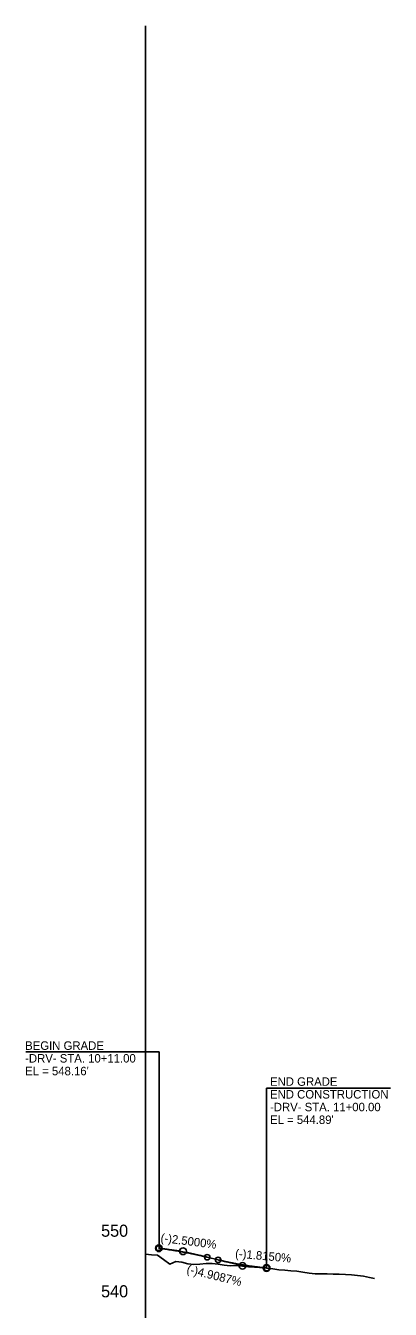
# Model space of a CAD drawing. Extents: x 1736530 to 1739201, y 695175 to 699135.
# Drawn here: x 1738900 to 1739201, y 696615 to 697675 of the extents above; entities that cross this region are included whole.
import ezdxf

# ---------------------------------------------------------------- set-up
doc = ezdxf.new("R2010")
doc.units = 0
for name, color, linetype in [('Exist Profile Cell', 7, 'Continuous'), ('Exist Vertical Profile Ground Line', 7, 'Continuous'), ('Exist Vertical Profile Vertical Axis Label', 7, 'Continuous'), ('Prop PFL Text', 7, 'Continuous'), ('Prop Vertical Profile Curve Label', 7, 'Continuous'), ('Prop Vertical Profile Grade', 7, 'Continuous'), ('Prop Vertical Profile Grade Label', 7, 'Continuous'), ('Prop VPI Label', 7, 'Continuous')]:
    doc.layers.add(name, color=color, linetype=linetype)

msp = doc.modelspace()

# ---------------------------------------------------------------- linework, layer by layer
at = {"layer": 'Exist Profile Cell'}
msp.add_line((1738999.2, 696424.5), (1738999.2, 697674.5), dxfattribs=at)
at = {"layer": 'Exist Vertical Profile Ground Line'}
msp.add_lwpolyline([(1738999.2, 696660.3), (1739004.2, 696659.9), (1739009.2, 696659.5), (1739014.2, 696656.1), (1739019.2, 696652.1), (1739024.2, 696654.3), (1739029.2, 696653.8), (1739034.2, 696652.4), (1739039.2, 696651.8), (1739044.2, 696652.3), (1739049.2, 696652.8), (1739054.2, 696652.8), (1739059.2, 696652.1), (1739064.2, 696651.3), (1739069.2, 696650.9), (1739074.2, 696651), (1739079.2, 696650.6), (1739084.2, 696650.1), (1739089.2, 696649.8), (1739094.2, 696649.5), (1739099.2, 696649), (1739104.2, 696648.4), (1739109.2, 696647.5), (1739114.2, 696647.1), (1739119.2, 696646.8), (1739124.2, 696646.4), (1739129.2, 696645.6), (1739134.2, 696644.8), (1739139.2, 696644.1), (1739144.2, 696644.1), (1739149.2, 696644.2), (1739154.2, 696644), (1739159.2, 696643.8), (1739164.2, 696643.6), (1739169.2, 696643.3), (1739174.2, 696642.7), (1739179.2, 696642.2), (1739184.2, 696641.1), (1739188.2, 696640.3)], dxfattribs=at)
at = {"layer": 'Prop Vertical Profile Curve Label'}
for centre in [(1739010.2, 696665.3), (1739050.2, 696657.9), (1739059.2, 696655.7), (1739099.2, 696649)]:
    msp.add_circle(centre, 2.25, dxfattribs=at)
at = {"layer": 'Prop Vertical Profile Grade'}
msp.add_line((1739050.2, 696657.9), (1739059.2, 696655.7), dxfattribs=at)
for points in [[(1739010.2, 696665.3), (1739011, 696665.2), (1739011.8, 696665.1), (1739012.6, 696665), (1739013.4, 696664.9), (1739014.2, 696664.8), (1739015, 696664.7), (1739015.8, 696664.6), (1739016.6, 696664.5), (1739017.4, 696664.4), (1739018.2, 696664.2), (1739019, 696664.1), (1739019.8, 696664), (1739020.6, 696663.9), (1739021.4, 696663.8), (1739022.2, 696663.6), (1739023, 696663.5), (1739023.8, 696663.4), (1739024.6, 696663.2), (1739025.4, 696663.1), (1739026.2, 696663), (1739027, 696662.8), (1739027.8, 696662.7), (1739028.6, 696662.5), (1739029.4, 696662.4), (1739030.2, 696662.2), (1739031, 696662.1), (1739031.8, 696661.9), (1739032.6, 696661.8), (1739033.4, 696661.6), (1739034.2, 696661.5), (1739035, 696661.3), (1739035.8, 696661.2), (1739036.6, 696661), (1739037.4, 696660.8), (1739038.2, 696660.7), (1739039, 696660.5), (1739039.8, 696660.3), (1739040.6, 696660.2), (1739041.4, 696660), (1739042.2, 696659.8), (1739043, 696659.6), (1739043.8, 696659.4), (1739044.6, 696659.3), (1739045.4, 696659.1), (1739046.2, 696658.9), (1739047, 696658.7), (1739047.8, 696658.5), (1739048.6, 696658.3), (1739049.4, 696658.1), (1739050.2, 696657.9)], [(1739059.2, 696655.7), (1739060, 696655.5), (1739060.8, 696655.3), (1739061.6, 696655.2), (1739062.4, 696655), (1739063.2, 696654.8), (1739064, 696654.6), (1739064.8, 696654.4), (1739065.6, 696654.2), (1739066.4, 696654.1), (1739067.2, 696653.9), (1739068, 696653.7), (1739068.8, 696653.6), (1739069.6, 696653.4), (1739070.4, 696653.2), (1739071.2, 696653.1), (1739072, 696652.9), (1739072.8, 696652.7), (1739073.6, 696652.6), (1739074.4, 696652.4), (1739075.2, 696652.3), (1739076, 696652.2), (1739076.8, 696652), (1739077.6, 696651.9), (1739078.4, 696651.7), (1739079.2, 696651.6), (1739080, 696651.5), (1739080.8, 696651.3), (1739081.6, 696651.2), (1739082.4, 696651.1), (1739083.2, 696651), (1739084, 696650.8), (1739084.8, 696650.7), (1739085.6, 696650.6), (1739086.4, 696650.5), (1739087.2, 696650.4), (1739088, 696650.3), (1739088.8, 696650.2), (1739089.6, 696650.1), (1739090.4, 696650), (1739091.2, 696649.9), (1739092, 696649.8), (1739092.8, 696649.7), (1739093.6, 696649.6), (1739094.4, 696649.5), (1739095.2, 696649.4), (1739096, 696649.3), (1739096.8, 696649.2), (1739097.6, 696649.2), (1739098.4, 696649.1), (1739099.2, 696649)]]:
    msp.add_spline(points, degree=3, dxfattribs=at)
at = {"layer": 'Prop VPI Label'}
for p, q in [((1738900.4, 696827.4), (1739010.6, 696827.4)), ((1739010.6, 696664.3), (1739010.6, 696827.4)), ((1739099.2, 696649), (1739099.1, 696797.4)), ((1739099.1, 696797.4), (1739201.3, 696797.4)), ((1739010.2, 696665.3), (1739027.4, 696663.2)), ((1739050.2, 696657.9), (1739032.8, 696662.2)), ((1739059.2, 696655.7), (1739076.5, 696651.5)), ((1739099.2, 696649), (1739081.9, 696650.6))]:
    msp.add_line(p, q, dxfattribs=at)
for centre in [(1739010.2, 696665.3), (1739030.2, 696662.8), (1739079.2, 696650.8), (1739099.2, 696649)]:
    msp.add_circle(centre, 2.75, dxfattribs=at)

# ---------------------------------------------------------------- texts
at = {"layer": 'Exist Vertical Profile Vertical Axis Label'}
for s, p in [('550', (1738962.6, 696674.8)), ('540', (1738962.6, 696624.8))]:
    msp.add_text(s, height=10, dxfattribs=at).set_placement(p)
at = {"layer": 'Prop PFL Text'}
for s, p in [('-DRV- STA. 10+11.00', (1738899.9, 696818.6)), ('BEGIN GRADE', (1738899.9, 696829.1)), ("EL = 548.16'", (1738899.9, 696808.1)), ('END GRADE', (1739102, 696799.4)), ('END CONSTRUCTION', (1739102, 696788.9)), ('-DRV- STA. 11+00.00', (1739102, 696778.4)), ("EL = 544.89'", (1739102, 696767.9))]:
    msp.add_text(s, height=7, dxfattribs=at).set_placement(p)
at = {"layer": 'Prop Vertical Profile Grade Label'}
for s, rotation, p in [('(-)2.5000%', 352.875, (1739011.4, 696670.6)), ('(-)1.8150%', 354.8146, (1739073, 696657.7)), ('(-)4.9087%', 346.2102, (1739032.7, 696645))]:
    msp.add_text(s, height=7, rotation=rotation, dxfattribs=at).set_placement(p)

doc.saveas('drawing.dxf')
